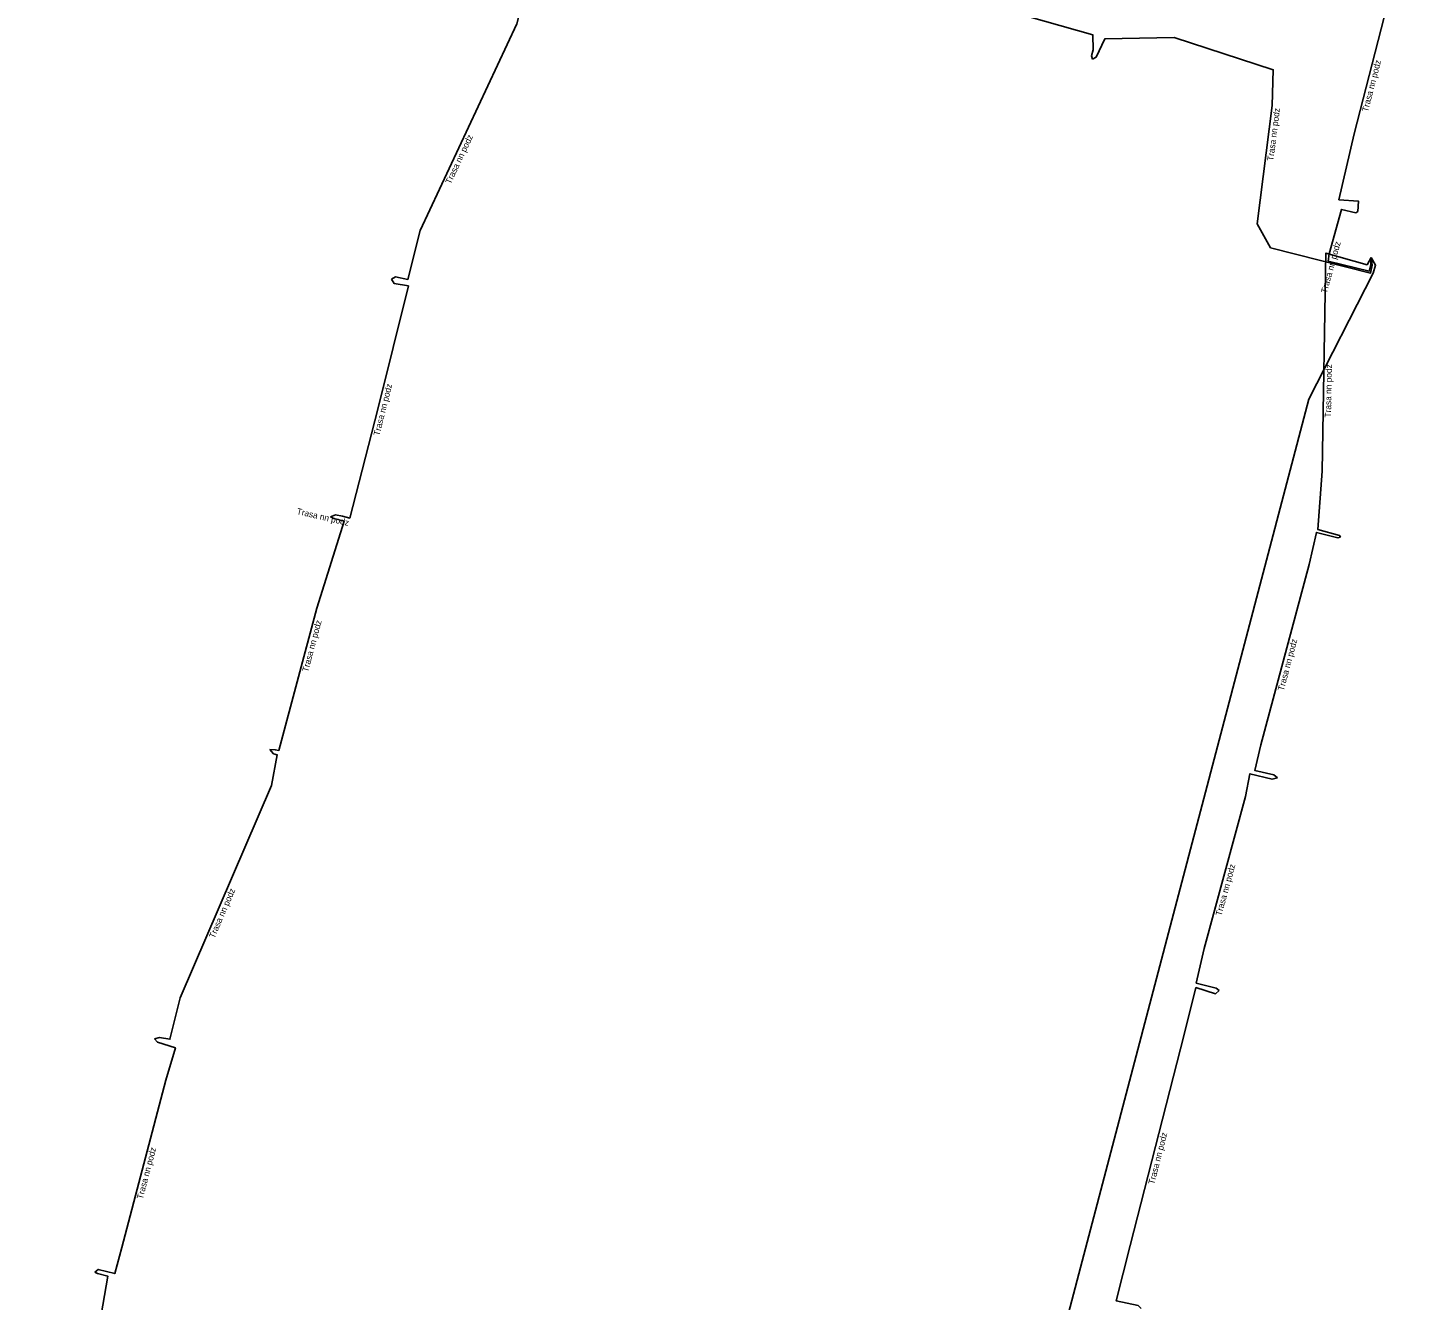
# Model space of a CAD drawing. Extents: x -843786 to -842968, y -1003095 to -1002172.
# Drawn here: x -843365.6 to -843253.2, y -1002899.3 to -1002797.2 of the extents above; entities that cross this region are included whole.
import ezdxf

# ---------------------------------------------------------------- set-up
doc = ezdxf.new("R2010")
doc.units = 0
doc.layers.add('Spojnice NN', color=7, linetype='Continuous')
doc.layers.add('Vrstva 20', color=7, linetype='Continuous')

msp = doc.modelspace()

# ---------------------------------------------------------------- linework, layer by layer
at = {"layer": 'Spojnice NN'}
for points in [[(-843253.21, -1002790.51), (-843253.56, -1002790.61), (-843255.21, -1002790.23), (-843256.24, -1002794.42), (-843259.14, -1002805.68), (-843260.35, -1002810.99), (-843258.78, -1002811.11), (-843258.83, -1002811.93)], [(-843298.08, -1002794.88), (-843297.9, -1002794.76), (-843297.22, -1002792.87), (-843280.11, -1002797.74), (-843280.08, -1002798.95), (-843280.2, -1002799.43), (-843280.12, -1002799.7)], [(-843336.39, -1002817.37), (-843336.08, -1002817.17), (-843335.08, -1002817.38), (-843334.09, -1002813.46), (-843326.32, -1002796.86), (-843326.08, -1002795.93), (-843327.02, -1002795.77), (-843327.13, -1002795.55)], [(-843280.12, -1002799.7), (-843279.85, -1002799.54), (-843279.14, -1002798.06), (-843273.57, -1002797.95), (-843265.62, -1002800.55), (-843265.71, -1002803.42), (-843266.92, -1002812.93), (-843265.84, -1002814.84), (-843257.81, -1002816.87), (-843257.69, -1002816.23), (-843257.76, -1002815.63)], [(-843258.83, -1002811.93), (-843259.01, -1002812.03), (-843260.15, -1002811.76), (-843261.13, -1002815.33), (-843261.21, -1002815.91), (-843257.94, -1002816.72), (-843257.8, -1002816.17), (-843257.8, -1002816.15), (-843257.76, -1002815.63)], [(-843257.76, -1002815.63), (-843258.09, -1002816.2), (-843261.4, -1002815.27), (-843261.71, -1002832.77), (-843262.06, -1002837.46), (-843260.3, -1002837.94), (-843260.23, -1002838.08)], [(-843257.76, -1002815.63), (-843257.41, -1002816.23), (-843257.61, -1002816.89), (-843262.78, -1002826.99), (-843284.09, -1002908.12), (-843288.58, -1002925.28), (-843292.89, -1002941.02), (-843292.8, -1002942.16), (-843290.49, -1002944.36), (-843290.52, -1002944.47), (-843288.57, -1002944.93), (-843277.94, -1002949.82), (-843282.83, -1002966.55), (-843283.98, -1002971.22), (-843285.91, -1002981.76), (-843290.95, -1003000.05), (-843302.43, -1002996.89), (-843303, -1002996.83)], [(-843340.32, -1002836.4), (-843339.74, -1002836.54), (-843337.49, -1002827.8), (-843335.03, -1002817.9), (-843336.18, -1002817.7), (-843336.39, -1002817.37)], [(-843346.15, -1002855.13), (-843345.72, -1002855.14), (-843345.44, -1002855.2), (-843342.38, -1002843.79), (-843340.19, -1002836.8), (-843341.02, -1002836.59), (-843341.3, -1002836.45)], [(-843341.3, -1002836.45), (-843340.89, -1002836.27), (-843340.32, -1002836.4)], [(-843260.23, -1002838.08), (-843260.43, -1002838.14), (-843262.16, -1002837.69), (-843262.75, -1002840.26), (-843266.61, -1002854.75), (-843267.1, -1002856.82), (-843265.57, -1002857.17), (-843265.28, -1002857.41)], [(-843355.4, -1002878.35), (-843355, -1002878.25), (-843354.17, -1002878.39), (-843353.34, -1002875.07), (-843346.01, -1002858.01), (-843345.56, -1002855.56), (-843345.86, -1002855.48), (-843346.15, -1002855.13)], [(-843265.28, -1002857.41), (-843265.72, -1002857.52), (-843267.5, -1002857.07), (-843267.84, -1002858.9), (-843271.16, -1002871.11), (-843271.8, -1002873.88), (-843270.22, -1002874.28), (-843269.97, -1002874.47)], [(-843269.97, -1002874.47), (-843270.26, -1002874.74), (-843271.83, -1002874.24), (-843272.77, -1002878.01), (-843277.1, -1002894.95), (-843278.23, -1002899.4), (-843276.47, -1002899.78), (-843276.22, -1002900.02)], [(-843360.2, -1002897.08), (-843359.92, -1002896.87), (-843358.6, -1002897.2), (-843358.04, -1002895.1), (-843354.51, -1002881.67), (-843353.73, -1002879.08), (-843355.17, -1002878.63), (-843355.4, -1002878.35)], [(-843365.56, -1002917.8), (-843365.28, -1002917.71), (-843364.64, -1002917.86), (-843364.19, -1002916.34), (-843359.7, -1002900.52), (-843359.15, -1002897.42), (-843359.98, -1002897.2), (-843360.2, -1002897.08)]]:
    msp.add_lwpolyline(points, dxfattribs=at)

# ---------------------------------------------------------------- texts
at = {"layer": 'Vrstva 20'}
for rotation, p in [(75.5755, (-843258.03, -1002803.97)), (82.7098, (-843265.62, -1002807.89)), (64.9104, (-843331.64, -1002809.77)), (74.6722, (-843261.33, -1002818.53)), (88.9832, (-843260.99, -1002828.47)), (76.0367, (-843337.36, -1002829.97)), (347.1203, (-843344.03, -1002836.22)), (75.0231, (-843343.09, -1002848.94)), (75.0942, (-843264.79, -1002850.45)), (74.8212, (-843269.78, -1002868.52)), (66.7577, (-843350.6, -1002870.33)), (75.6661, (-843275.18, -1002890.08)), (75.2457, (-843356.36, -1002891.27))]:
    msp.add_text('Trasa nn podz', height=0.5, rotation=rotation, dxfattribs=at).set_placement(p)

doc.saveas('drawing.dxf')
